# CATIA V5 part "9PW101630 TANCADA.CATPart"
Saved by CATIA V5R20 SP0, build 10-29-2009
Part number: 9PW101630 TANCADA
Revision: ANY
Definition: UNKNOWN
Nomenclature: 9PW101630 TANCADA
Source: Unknown
Bounding box of the stored display mesh (mm): x -175 to 0, y -8.113 to 5.5, z -8.1 to 8.1
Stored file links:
  C:\Users\Utente\Desktop\IO LAVORO\3D X SITO CF\CUMSA\3D files PW\pw101630\pw101630_injection\9PW101630 TANCADA.CATPart
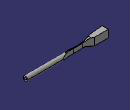
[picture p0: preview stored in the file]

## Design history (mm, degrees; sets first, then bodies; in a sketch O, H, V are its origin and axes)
Body1 "Chaflán5" (main body)
  Solid1: solid without history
